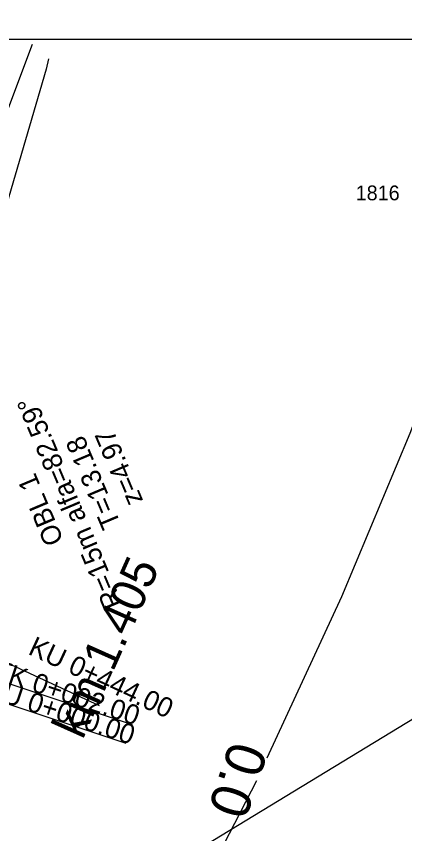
# Model space of a CAD drawing. Extents: x -583721 to -583071, y -1166145 to -1165065.
# Drawn here: x -583434.3 to -583394.9, y -1165247.5 to -1165164.5 of the extents above; entities that cross this region are included whole.
import ezdxf

# ---------------------------------------------------------------- set-up
doc = ezdxf.new("R2010")
doc.units = 0
for name, color, linetype in [('01_DOPRAVA', 7, 'Continuous'), ('21', 7, 'Continuous'), ('56', 7, 'Continuous'), ('Kabel_navrh', 7, 'Continuous'), ('Parcelní čísla', 7, 'Continuous'), ('Popis PP', 7, 'Continuous'), ('TISK', 7, 'Continuous')]:
    doc.layers.add(name, color=color, linetype=linetype)

msp = doc.modelspace()

# ---------------------------------------------------------------- linework, layer by layer
at = {"layer": '01_DOPRAVA'}
for points in [[(-583447.13, -1165205.68), (-583432.726, -1165167.34)], [(-583322.15, -1165168.47), (-583340.5, -1165179.46), (-583360.81, -1165200.75), (-583377.25, -1165221.89), (-583390.68, -1165233.74), (-583416.76, -1165249.61), (-583440.61, -1165276.22), (-583445.47, -1165291.1), (-583456.44, -1165295.04)]]:
    msp.add_lwpolyline(points, dxfattribs=at)
at = {"layer": '56'}
msp.add_lwpolyline([(-583516.969, -1166111.821), (-583516.969, -1165166.821), (-583071.469, -1165166.821), (-583071.469, -1166111.821)], close=True, dxfattribs=at)
at = {"layer": 'Kabel_navrh'}
for points in [[(-583431.078, -1165168.845), (-583431.34, -1165169.87)], [(-583431.34, -1165169.87), (-583442.72, -1165208.75)]]:
    msp.add_lwpolyline(points, dxfattribs=at)
at = {"layer": 'Popis PP'}
for points in [[(-583408.884, -1165239.761), (-583401.305, -1165223.395), (-583394.394, -1165206.814), (-583389.418, -1165193.591), (-583384.692, -1165179.916), (-583376.753, -1165154.163), (-583368.72, -1165125.582), (-583362.117, -1165101.519), (-583360.801, -1165096.713)], [(-583678.905, -1165475.483), (-583657.327, -1165467.488), (-583642.703, -1165461.447), (-583622.622, -1165452.387), (-583599.731, -1165440.633), (-583577.819, -1165427.732), (-583559.147, -1165415.353), (-583547.537, -1165406.998), (-583529.767, -1165393.094), (-583516.078, -1165381.407), (-583505.308, -1165371.528), (-583489.515, -1165355.792), (-583475.232, -1165340.013), (-583462.903, -1165325.35), (-583448.483, -1165306.372), (-583434.881, -1165286.276), (-583426.973, -1165273.475), (-583417.157, -1165256.037), (-583409.955, -1165242.074)]]:
    msp.add_lwpolyline(points, dxfattribs=at)
at = {"layer": 'TISK'}
for points in [[(-583448.636, -1165223.926), (-583425.962, -1165234.456)], [(-583446.333, -1165228.49), (-583422.612, -1165236.384)], [(-583446.965, -1165230.388), (-583423.244, -1165238.281)]]:
    msp.add_lwpolyline(points, dxfattribs=at)

# ---------------------------------------------------------------- texts
at = {"layer": '21'}
msp.add_text('km 1.405', height=3.5, rotation=65.91964, dxfattribs=at).set_placement((-583427.627, -1165238.01))
at = {"layer": 'Parcelní čísla'}
msp.add_text('1816', height=1.5, dxfattribs=at).set_placement((-583399.915, -1165183.186))
at = {"layer": 'TISK'}
for s, height, rotation, p in [('R=15m alfa=82.59%%d', 2, 112.89076, (-583423.537, -1165224.165)), ('  T=13.18', 2, 112.89076, (-583423.139, -1165217.395)), ('   z=4.97', 2, 112.89076, (-583420.588, -1165215.725)), ('OBL 1', 2, 112.89076, (-583429.513, -1165217.725)), ('KU 0+444.00', 2, 335.08822, (-583433.261, -1165229.198)), ('TK 0+002.00', 2, 341.59432, (-583436.845, -1165231.648)), ('ZU 0+000.00', 2, 341.59432, (-583437.476, -1165233.545)), ('0.0', 4, 251.59432, (-583412.572, -1165237.882))]:
    msp.add_text(s, height=height, rotation=rotation, dxfattribs=at).set_placement(p)

doc.saveas('drawing.dxf')
